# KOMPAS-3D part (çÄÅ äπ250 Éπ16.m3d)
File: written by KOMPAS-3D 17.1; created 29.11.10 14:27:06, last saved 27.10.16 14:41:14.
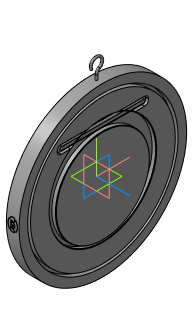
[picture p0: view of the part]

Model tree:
1. Плоскость XY
2. Плоскость ZX
3. Плоскость ZY
4. Ось X
5. Ось Y
6. Ось Z
7. Начало координат
8. Операция без истории:2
